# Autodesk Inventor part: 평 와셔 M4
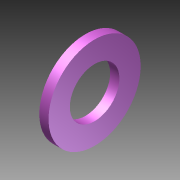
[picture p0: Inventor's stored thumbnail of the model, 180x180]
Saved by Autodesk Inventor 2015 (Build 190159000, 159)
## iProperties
Created: 2026-04
Part Number: 평 와셔 M4
Material: 일반
Document SubType Name: Modeling
Designer: User
Density: 1 g/cm^3
Appearance: 기본값
Author: User
Author: jhkim
Description: 평면 와셔
Creation Date: 2026-03-26
Sending System: Autodesk Inventor 2026
Preprocessor: ST-DEVELOPER v20.1
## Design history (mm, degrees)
node "평 와셔 M41"
body "Solid1"
node "기준1"
